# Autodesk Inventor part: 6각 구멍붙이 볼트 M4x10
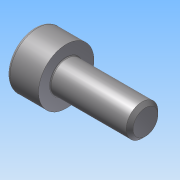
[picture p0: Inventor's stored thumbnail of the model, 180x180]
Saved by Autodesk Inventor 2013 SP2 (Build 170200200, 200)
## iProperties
Created: 2025-10
Part Number: 6각 구멍붙이 볼트 M4x10
Material: Generic
Document SubType Name: Modeling
Designer: a
Density: 1 g/cm^3
Author: a
변환 표준: STEP AP214IS
전처리기: Build: 200, Release: 2013 SP2 Update 6 - Date: Thu 07/17/2014
전송 단위: 밀리미터
불확실성: 0.01
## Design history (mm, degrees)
node "6각 구멍붙이 볼트 M4x101"
body "Solid1"
node "기준1"
